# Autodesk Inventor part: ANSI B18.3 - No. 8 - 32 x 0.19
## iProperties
Shininess: 41.0
Length Units: 11272
Angle Units: 11279
Time Units: 11290
Mass Units: 11286
Length Display Precision: 4
Angle Display Precision: 2
Compacted: True
Company: Autodesk
Manager: Lebovitz
Created: 2000-11
Part Number: ANSI B18.3 - No. 8 - 32 x 0.19
Description: Hexagon Socket Set Screw - Flat Point
Document SubType Name: Modeling
Standard: ANSI B18.3 - No. 8 - 32 x 0.19
Designer: The PD Team
Project: Inventor Samples
Checked By: The PD Team
Density: 0.0
Volumn: 0.0
Area: 0.0
PropertySet Name: Model Information
Control State: 0
Master: False
Checked Out: False
Author: The PD Team
Revision Number: A
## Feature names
1. Base1
